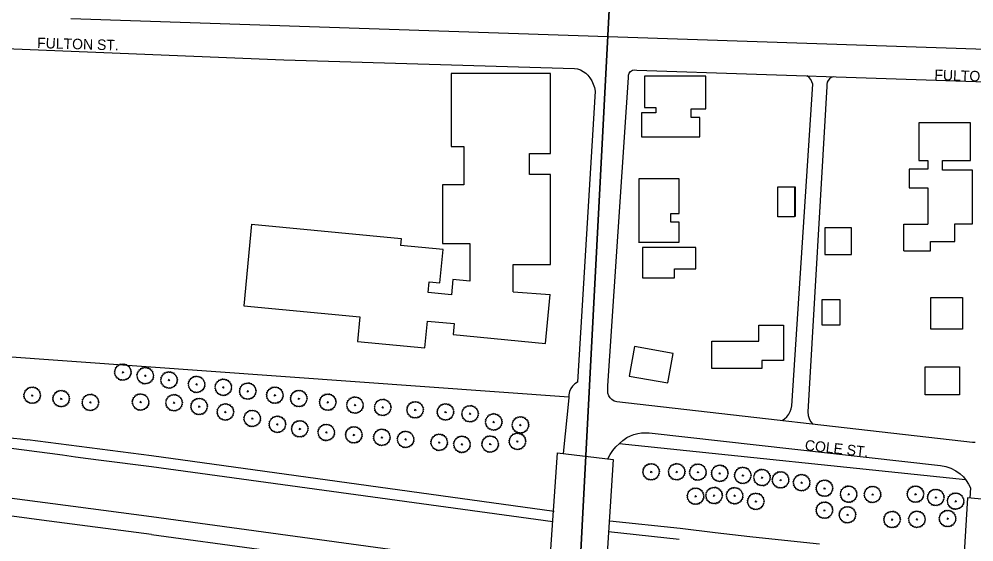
# Model space of a CAD drawing. Extents: x -9648 to 41057, y -12373 to 40276.
# Drawn here: x 11921 to 12833, y -4917 to -4417 of the extents above; entities that cross this region are included whole.
import ezdxf

# ---------------------------------------------------------------- set-up
doc = ezdxf.new("R2010")
doc.units = 0
for name, color, linetype in [('Default', 7, 'Continuous'), ('PM_X_Stop_Line', 7, 'Continuous'), ('SC_Scratch1', 7, 'Continuous'), ('SH_Data', 7, 'Continuous')]:
    doc.layers.add(name, color=color, linetype=linetype)

# ---------------------------------------------------------------- blocks, each defined once
blk = doc.blocks.new('15_PIN')
at = {"layer": 'Default'}
for p, q in [((-2.8, 0), (2.8, 0)), ((0, 2.8), (0, -2.8))]:
    blk.add_line(p, q, dxfattribs=at)
for centre, start, end in [((-25.5, 4.5), 275.99, 64.01), ((-25.9, -1.5), 289.3234, 77.3433), ((-23.8, 10.3), 262.6567, 50.6766), ((-20.8, 15.5), 249.3234, 37.3433), ((-16.7, 19.8), 235.99, 24.01), ((-11.6, 23.2), 222.6567, 10.6766), ((-6, 25.2), 209.3234, 357.3433), ((0, 25.9), 195.99, 344.01), ((6, 25.2), 182.6567, 330.6766), ((11.6, 23.2), 169.3234, 317.3433), ((16.7, 19.8), 155.99, 304.01), ((20.8, 15.5), 142.6567, 290.6766), ((23.8, 10.3), 129.3234, 277.3433), ((25.5, 4.5), 115.99, 264.01), ((25.9, -1.5), 102.6567, 250.6766), ((-24.8, -7.4), 302.6567, 90.6766), ((-22.4, -13), 315.99, 104.01), ((-18.8, -17.8), 329.3234, 117.3433), ((-14.2, -21.6), 342.6567, 130.6766), ((-8.9, -24.3), 355.99, 144.01), ((-3, -25.7), 9.3234, 157.3433), ((3, -25.7), 22.6567, 170.6766), ((8.9, -24.3), 35.99, 184.01), ((14.2, -21.6), 49.3234, 197.3433), ((18.8, -17.8), 62.6567, 210.6767), ((22.4, -13), 75.99, 224.01), ((24.8, -7.4), 89.3234, 237.3433)]:
    blk.add_arc(centre, 3.05, start, end, dxfattribs=at)

msp = doc.modelspace()

# ---------------------------------------------------------------- linework, layer by layer
at = {"layer": 'PM_X_Stop_Line'}
msp.add_arc((9361.23, -8468.95), 3904.03, 82.5, 82.5, dxfattribs=at)
at = {"layer": 'SC_Scratch1'}
for p, q in [((12492.94, -4255.51), (12411.7, -5793.36)), ((12411.7, -5793.36), (12492.94, -4255.51)), ((12492.94, -4255.51), (12411.7, -5793.36))]:
    msp.add_line(p, q, dxfattribs=at)
at = {"layer": 'SH_Data'}
for p, q in [((11970.42, -4416.72), (13142.88, -4456.26)), ((11806.04, -4441.22), (12174.08, -4456.26)), ((12174.08, -4456.26), (12451.48, -4464.46)), ((12451.48, -4464.46), (12454.38, -4464.96)), ((12454.38, -4464.96), (12457.28, -4465.96)), ((12457.28, -4465.96), (12459.88, -4467.26)), ((12459.88, -4467.26), (12462.38, -4469.06)), ((12503.78, -4469.06), (12505.18, -4467.36)), ((12505.18, -4467.36), (12506.98, -4466.26)), ((12506.98, -4466.26), (12509.18, -4465.76)), ((12509.18, -4465.76), (12511.28, -4466.06)), ((12511.28, -4466.06), (12857.28, -4477.66)), ((12428.77, -4469.37), (12333.79, -4469.37)), ((12333.79, -4469.37), (12333.79, -4538.95)), ((12428.77, -4545.69), (12428.77, -4469.37)), ((12462.38, -4469.06), (12464.48, -4471.06)), ((12464.48, -4471.06), (12466.28, -4473.46)), ((12466.28, -4473.46), (12468.08, -4476.36)), ((12468.08, -4476.36), (12469.48, -4479.46)), ((12483.28, -4767.86), (12503.08, -4473.26)), ((12503.08, -4471.06), (12503.78, -4469.06)), ((12503.08, -4473.26), (12503.08, -4471.06)), ((12577.18, -4471.72), (12518.47, -4471.72)), ((12518.47, -4471.72), (12518.47, -4501.76)), ((12577.18, -4503.13), (12577.18, -4471.72)), ((12675.68, -4473.16), (12673.68, -4471.46)), ((12677.18, -4475.06), (12675.68, -4473.16)), ((12678.38, -4477.26), (12677.18, -4475.06)), ((12679.08, -4479.66), (12678.38, -4477.26)), ((12693.88, -4475.96), (12692.98, -4477.76)), ((12695.18, -4474.36), (12693.88, -4475.96)), ((12696.88, -4473.16), (12695.18, -4474.36)), ((12698.78, -4472.36), (12696.88, -4473.16)), ((12471.48, -4486.06), (12454.48, -4764.26)), ((12469.48, -4479.46), (12470.68, -4482.76)), ((12470.68, -4482.76), (12471.48, -4486.06)), ((12659.28, -4786.86), (12679.08, -4479.66)), ((12692.68, -4481.86), (12674.48, -4792.86)), ((12692.98, -4477.76), (12692.58, -4479.86)), ((12692.58, -4479.86), (12692.68, -4481.86)), ((12518.47, -4501.76), (12529.39, -4501.76)), ((12529.39, -4501.76), (12529.39, -4506.77)), ((12563.07, -4511.32), (12563.07, -4503.13)), ((12563.07, -4503.13), (12577.18, -4503.13)), ((12529.39, -4506.77), (12515.74, -4506.77)), ((12515.74, -4506.77), (12515.74, -4529.99)), ((12571.26, -4511.32), (12563.07, -4511.32)), ((12571.26, -4529.99), (12571.26, -4511.32)), ((12829.76, -4516.61), (12780.6, -4516.61)), ((12780.6, -4516.61), (12780.6, -4552.38)), ((12829.76, -4552.38), (12829.76, -4516.61)), ((12515.74, -4529.99), (12557.15, -4529.99)), ((12557.15, -4529.99), (12571.26, -4529.99)), ((12333.79, -4538.95), (12345.75, -4538.95)), ((12345.75, -4538.95), (12345.75, -4575.6)), ((12408.57, -4565.88), (12408.57, -4545.69)), ((12408.57, -4545.69), (12428.77, -4545.69)), ((12780.6, -4552.38), (12789.04, -4552.38)), ((12789.04, -4552.38), (12789.04, -4560.82)), ((12802.94, -4561.81), (12802.94, -4552.38)), ((12802.94, -4552.38), (12829.76, -4552.38)), ((12428.77, -4565.88), (12408.57, -4565.88)), ((12428.77, -4651.91), (12428.77, -4565.88)), ((12789.04, -4560.82), (12771.16, -4560.82)), ((12771.16, -4560.82), (12771.16, -4578.69)), ((12831.75, -4561.81), (12802.94, -4561.81)), ((12831.75, -4612.97), (12831.75, -4561.81)), ((12345.75, -4575.6), (12325.56, -4575.6)), ((12325.56, -4575.6), (12325.56, -4631.71)), ((12551.69, -4570.05), (12513.01, -4570.05)), ((12513.01, -4570.05), (12513.01, -4631.05)), ((12551.69, -4603.29), (12551.69, -4570.05)), ((12645.9, -4606.38), (12645.9, -4577.79)), ((12645.9, -4577.79), (12662.28, -4577.79)), ((12661.82, -4577.79), (12661.82, -4606.38)), ((12662.28, -4577.79), (12662.28, -4605.92)), ((12771.16, -4578.69), (12789.04, -4578.69)), ((12789.04, -4578.69), (12789.04, -4613.47)), ((12543.5, -4611.48), (12543.5, -4603.29)), ((12543.5, -4603.29), (12551.69, -4603.29)), ((12143.11, -4613.43), (12135.69, -4691.35)), ((12143.11, -4613.43), (12286.12, -4627.04)), ((12551.69, -4611.48), (12543.5, -4611.48)), ((12551.69, -4630.6), (12551.69, -4611.48)), ((12661.82, -4606.38), (12645.9, -4606.38)), ((12766.2, -4638.8), (12766.2, -4613.47)), ((12766.2, -4613.47), (12789.04, -4613.47)), ((12814.86, -4629.86), (12814.86, -4612.97)), ((12814.86, -4612.97), (12831.75, -4612.97)), ((12690.72, -4616.95), (12690.72, -4642.28)), ((12716.06, -4616.95), (12690.72, -4616.95)), ((12716.06, -4642.28), (12716.06, -4616.95)), ((12286.12, -4627.04), (12285.49, -4633.68)), ((12325.56, -4631.71), (12351.74, -4631.71)), ((12351.74, -4631.71), (12351.74, -4667.88)), ((12513.01, -4630.6), (12551.69, -4630.6)), ((12791.53, -4638.8), (12791.53, -4629.86)), ((12791.53, -4629.86), (12814.86, -4629.86)), ((12326.07, -4637.54), (12285.49, -4633.68)), ((12323.03, -4669.47), (12326.07, -4637.54)), ((12516.65, -4635.62), (12516.65, -4664.74)), ((12567.62, -4635.62), (12516.65, -4635.62)), ((12567.62, -4656.09), (12567.62, -4635.62)), ((12766.2, -4638.8), (12791.53, -4638.8)), ((12690.72, -4642.28), (12716.06, -4642.28)), ((12392.87, -4678.09), (12392.87, -4651.91)), ((12392.87, -4651.91), (12428.77, -4651.91)), ((12547.15, -4664.74), (12547.15, -4656.09)), ((12547.15, -4656.09), (12567.62, -4656.09)), ((12311.91, -4678.66), (12312.87, -4668.5)), ((12312.87, -4668.5), (12323.03, -4669.47)), ((12335.45, -4666.33), (12334.08, -4680.77)), ((12351.74, -4667.88), (12335.45, -4666.33)), ((12516.65, -4664.74), (12547.15, -4664.74)), ((12334.08, -4680.77), (12311.91, -4678.66)), ((12392.87, -4678.09), (12428.27, -4680.53)), ((12423.82, -4727.27), (12428.27, -4680.53)), ((12688.24, -4709.83), (12688.24, -4685.49)), ((12688.24, -4685.49), (12705.12, -4685.49)), ((12705.12, -4685.49), (12705.12, -4709.83)), ((12792.02, -4713.81), (12792.02, -4683.52)), ((12792.02, -4683.52), (12822.31, -4683.52)), ((12822.31, -4683.52), (12822.31, -4713.81)), ((12135.69, -4691.35), (12246.52, -4701.9)), ((12246.52, -4701.9), (12244.28, -4725.4)), ((12308.67, -4731.53), (12311.1, -4705.99)), ((12311.1, -4705.99), (12336.63, -4708.43)), ((12336.63, -4708.43), (12335.64, -4718.87)), ((12627.69, -4725.29), (12627.69, -4709.81)), ((12627.69, -4709.81), (12651.36, -4709.81)), ((12651.36, -4709.81), (12651.36, -4743.5)), ((12705.12, -4709.83), (12688.24, -4709.83)), ((12822.31, -4713.81), (12792.02, -4713.81)), ((12335.64, -4718.87), (12423.82, -4727.27)), ((11789.19, -4731.17), (12446.08, -4778.36)), ((12244.28, -4725.4), (12308.67, -4731.53)), ((12508.92, -4730.26), (12503.91, -4758.52)), ((12545.83, -4736.81), (12508.92, -4730.26)), ((12582.64, -4751.24), (12582.64, -4725.29)), ((12582.64, -4725.29), (12627.69, -4725.29)), ((12540.82, -4765.07), (12545.83, -4736.81)), ((12651.36, -4743.5), (12630.42, -4743.5)), ((12630.42, -4743.5), (12630.42, -4751.24)), ((12786.56, -4776.39), (12786.56, -4749.57)), ((12786.56, -4749.57), (12819.33, -4749.57)), ((12819.33, -4749.57), (12819.33, -4776.39)), ((12503.91, -4758.52), (12540.82, -4765.07)), ((12630.42, -4751.24), (12582.64, -4751.24)), ((12449.68, -4768.06), (12447.98, -4770.56)), ((12451.88, -4765.96), (12449.68, -4768.06)), ((12454.48, -4764.26), (12451.88, -4765.96)), ((12483.28, -4772.46), (12483.28, -4767.86)), ((12446.78, -4773.36), (12446.08, -4776.36)), ((12446.08, -4776.36), (12446.08, -4779.46)), ((12447.98, -4770.56), (12446.78, -4773.36)), ((12483.48, -4774.96), (12483.28, -4772.46)), ((12484.28, -4777.26), (12483.48, -4774.96)), ((12485.58, -4779.36), (12484.28, -4777.26)), ((12819.33, -4776.39), (12786.56, -4776.39)), ((12446.08, -4779.46), (12440.68, -4832.46)), ((12487.38, -4781.06), (12485.58, -4779.36)), ((12489.48, -4782.36), (12487.38, -4781.06)), ((12491.88, -4783.06), (12489.48, -4782.36)), ((12831.68, -4821.86), (12491.88, -4783.06)), ((12658.68, -4789.76), (12659.28, -4786.86)), ((12654.38, -4797.36), (12656.18, -4795.06)), ((12656.18, -4795.06), (12657.58, -4792.46)), ((12657.58, -4792.46), (12658.68, -4789.76)), ((12674.48, -4792.86), (12674.68, -4796.06)), ((12674.68, -4796.06), (12675.58, -4799.16)), ((12649.88, -4801.06), (12652.28, -4799.46)), ((12652.28, -4799.46), (12654.38, -4797.36)), ((12675.58, -4799.16), (12677.08, -4801.96)), ((12677.08, -4801.96), (12679.18, -4804.46)), ((12504.98, -4815.66), (12508.38, -4814.36)), ((12508.38, -4814.36), (12511.98, -4813.46)), ((12511.98, -4813.46), (12515.58, -4812.86)), ((12515.58, -4812.86), (12519.18, -4812.66)), ((12519.18, -4812.66), (12522.88, -4812.86)), ((12522.88, -4812.86), (12801.08, -4843.86)), ((12047.66, -4834.88), (11929.05, -4819.35)), ((12491.18, -4826.26), (12494.48, -4822.96)), ((12494.32, -4823.11), (12824.92, -4857.3)), ((12494.48, -4822.96), (12497.88, -4819.96)), ((12497.88, -4819.96), (12501.68, -4817.26)), ((12501.68, -4817.26), (12504.98, -4815.66)), ((12834.38, -4821.96), (12831.68, -4821.86)), ((12418.48, -5079.16), (12435.28, -4831.86)), ((12435.28, -4831.86), (12488.68, -4838.26)), ((12485.78, -4833.56), (12488.28, -4829.76)), ((12488.28, -4829.76), (12491.18, -4826.26)), ((12047.67, -4845.28), (11999.47, -4839.31)), ((12432.09, -4887.95), (12047.66, -4834.88)), ((12488.68, -4838.26), (12472.68, -5083.66)), ((12483.58, -4837.66), (12485.78, -4833.56)), ((12430.78, -4897.86), (12047.67, -4845.28)), ((12801.08, -4843.86), (12806.18, -4844.96)), ((12806.18, -4844.96), (12811.18, -4846.66)), ((12811.18, -4846.66), (12815.78, -4849.06)), ((12815.78, -4849.06), (12820.08, -4852.06)), ((12820.08, -4852.06), (12823.08, -4854.96)), ((12823.08, -4854.96), (12825.68, -4858.26)), ((12825.68, -4858.26), (12827.98, -4861.76)), ((12827.98, -4861.76), (12829.88, -4865.46)), ((12829.88, -4865.46), (12829.18, -4875.26)), ((12826.88, -4875.06), (12811.88, -5119.86)), ((12881.48, -4879.86), (12826.88, -4875.06)), ((12427.58, -4944.96), (12047.69, -4893.08)), ((12552.52, -4904.32), (12485.22, -4897.22)), ((12585.87, -4908.33), (12552.67, -4904.33)), ((12047.7, -4910.08), (12411.88, -4959.26)), ((12484.18, -4907.16), (12551.48, -4914.26)), ((12619.11, -4912.13), (12585.81, -4908.33)), ((12652.28, -4915.82), (12619.08, -4912.12)), ((12685.52, -4919.32), (12652.22, -4915.82))]:
    msp.add_line(p, q, dxfattribs=at)
for points in [[(12047.7, -4910.08), (11942.71, -4896.14), (11817.04, -4879.4), (11691.29, -4863.48), (11560.39, -4845.94), (11429.47, -4828.63), (11331.84, -4815.68), (11234.25, -4802.54), (11074.24, -4781.43), (11027.15, -4774.45)], [(12047.69, -4893.08), (11972.7, -4883.12), (11872.75, -4870.19), (11772.87, -4856.84), (11694.87, -4846.65), (11616.86, -4836.52), (11490.76, -4819.79), (11364.65, -4803.27), (11270.3, -4790.73), (11176.03, -4777.57)]]:
    msp.add_lwpolyline(points, dxfattribs=at)
for centre, radius, start, end in [((13377.37, 6870.23), 11778.96, 261.908183, 262.937183), ((10377.43, -16557.43), 11829.85, 82.119183, 83.077183)]:
    msp.add_arc(centre, radius, start, end, dxfattribs=at)

# ---------------------------------------------------------------- block references
at = {"layer": 'SH_Data', "xscale": 0.32808397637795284, "yscale": 0.32808397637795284, "rotation": 64.61472397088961}
for p in [(12020.28, -4754.76), (12041.66, -4758.15), (12064.35, -4762.32), (12090.68, -4766.49), (12116.21, -4769.26), (12116.21, -4769.26), (11933.7, -4776.86), (11961.35, -4780.06), (12139.54, -4772.92), (12165.43, -4776.8), (12188.31, -4780), (11989.25, -4783.71), (12037.19, -4783.36), (12069.15, -4784.02), (12093.13, -4787.59), (12215.96, -4783.49), (12241.95, -4786.25), (12268.43, -4788.52), (12118.18, -4792.86), (12299.41, -4790.78), (12328.4, -4792.8), (12351.87, -4794.56), (12143.83, -4799.02), (12167.85, -4804.66), (12374.44, -4802.39), (12399.92, -4805.22), (12189.25, -4808.95), (12214.53, -4812.4), (12240.88, -4814.72), (12267.63, -4817.07), (12290.29, -4819.06), (12322.4, -4821.88), (12344.13, -4823.79), (12371.09, -4823.5), (12397.09, -4820.93), (12524.82, -4850.03), (12549.2, -4850.03), (12569.47, -4850.33), (12590.33, -4851.48), (12612.37, -4853.45), (12630.69, -4855.52), (12648.43, -4857.74), (12668.52, -4860.38), (12690.35, -4865.75), (12713.43, -4871.41), (12777.3, -4871.4), (12567.21, -4873.33), (12584.91, -4872.7), (12604.55, -4872.9), (12624.77, -4878.29), (12736.28, -4871.68), (12796.69, -4874.53), (12815.59, -4878.06), (12690.32, -4886.74), (12712.36, -4891.11), (12754.93, -4895.62), (12778.65, -4895.41), (12807.93, -4894.7)]:
    msp.add_blockref('15_PIN', p, dxfattribs=at)

# ---------------------------------------------------------------- texts
at = {"layer": 'SC_Scratch1'}
for s, rotation, p in [('FULTON ST.', 358.32359, (11938.25, -4445.01)), ('FULTON ST.', 358.07981, (12795.19, -4475.51)), ('COLE ST.', 353.64173, (12671.25, -4829.32))]:
    msp.add_text(s, height=10, rotation=rotation, dxfattribs=at).set_placement(p)

doc.saveas('drawing.dxf')
